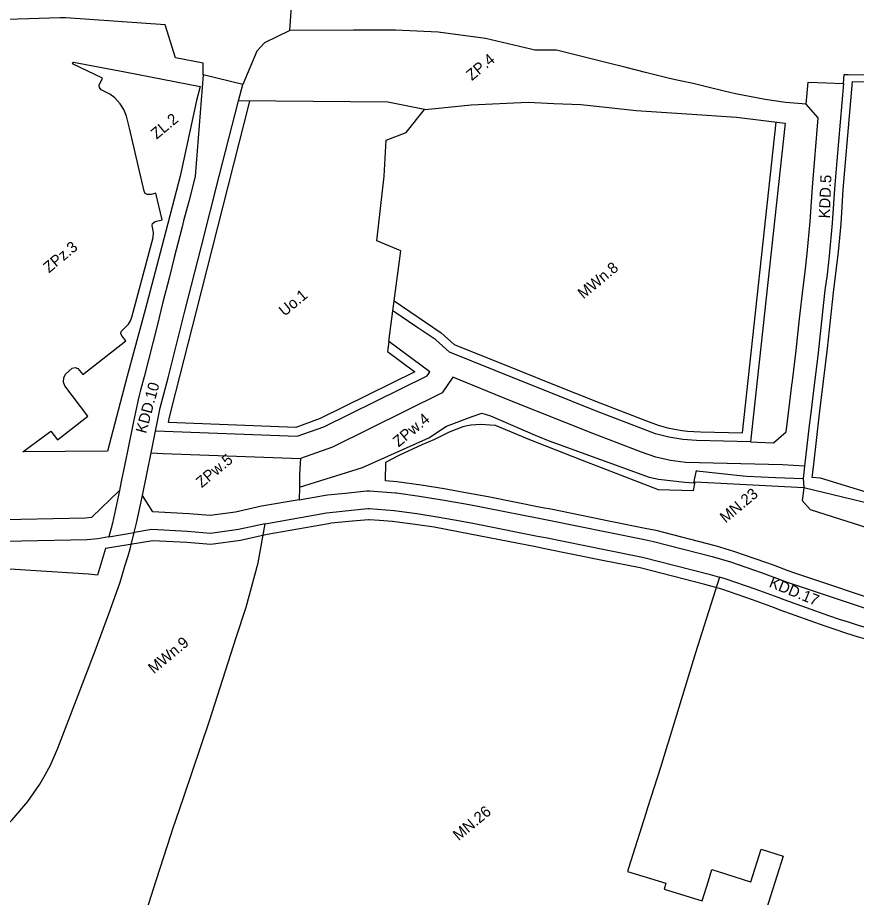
# Model space of a CAD drawing. Extents: x 7418616 to 7420822, y 5550745 to 5553106.
# Drawn here: x 7419553.4 to 7419932.5, y 5552057.3 to 5552455 of the extents above; entities that cross this region are included whole.
import ezdxf

# ---------------------------------------------------------------- set-up
doc = ezdxf.new("R2010")
doc.units = 0
for name, color, linetype in [('linie rozgraniczające', 7, 'Continuous'), ('nieprzekraczalne linie zabudowy', 7, 'Continuous'), ('przeznaczenia terenów', 7, 'Continuous')]:
    doc.layers.add(name, color=color, linetype=linetype)

msp = doc.modelspace()

# ---------------------------------------------------------------- linework, layer by layer
at = {"layer": 'linie rozgraniczające'}
for p, q in [((7419655.14, 5552424.74), (7419637.2, 5552429.07)), ((7419653.25, 5552417.32), (7419655.14, 5552424.74)), ((7419609.8, 5552239.02), (7419613.73, 5552258.19)), ((7419909.13, 5552252.2), (7419908.48, 5552246.57)), ((7419680.75, 5552242.72), (7419680.72, 5552237.05)), ((7419594.63, 5552220.26), (7419606.15, 5552222.19))]:
    msp.add_line(p, q, dxfattribs=at)
for points in [[(7419676.51, 5552449.1), (7419678.57, 5552479.45), (7419677.27, 5552480.3), (7419678.28, 5552486.89), (7419680.25, 5552499.71)], [(7419637.2, 5552429.07), (7419637.23, 5552434.4), (7419624.8, 5552436.75), (7419620.16, 5552451.72), (7419575.16, 5552454.94), (7419572.63, 5552454.93), (7419539.06, 5552453.86), (7419527.6, 5552453.48), (7419520.77, 5552453.24)], [(7419676.51, 5552449.1), (7419664.95, 5552443.58), (7419661.56, 5552439.85), (7419655.14, 5552424.74)], [(7419909.82, 5552415.87), (7419900.43, 5552416.68), (7419891.31, 5552417.98), (7419877.93, 5552420.55), (7419872.75, 5552421.81), (7419865.43, 5552423.52), (7419858.74, 5552425.16), (7419852.81, 5552426.42), (7419848.03, 5552427.53), (7419837.21, 5552430.25), (7419828.49, 5552432.39), (7419819.88, 5552434.54), (7419797.04, 5552440.3), (7419787.21, 5552440.32), (7419785.3, 5552440.79), (7419764.88, 5552445.51), (7419743.46, 5552448.48), (7419724.18, 5552449.27), (7419705.17, 5552449.29), (7419676.51, 5552449.1)], [(7419635.87, 5552423.79), (7419634.27, 5552417.47), (7419626.89, 5552383.27), (7419618.55, 5552351.58), (7419611.08, 5552322.83), (7419602.9, 5552292.94), (7419594.08, 5552258.93), (7419555.81, 5552258.67), (7419568.35, 5552268.03), (7419571.41, 5552264.07), (7419585.22, 5552274.87), (7419574.68, 5552288.52), (7419574.2, 5552290.15), (7419574.25, 5552292.07), (7419574.98, 5552293.76), (7419578.12, 5552296.52), (7419579.38, 5552296.83), (7419580.56, 5552296.42), (7419582.84, 5552293.71), (7419602.38, 5552308.85), (7419600.59, 5552310.93), (7419600.09, 5552312.11), (7419600.17, 5552313.11), (7419601.2, 5552314.22), (7419603.46, 5552316.36), (7419604.45, 5552317.98), (7419605.1, 5552319.53), (7419614.72, 5552355.64), (7419614.79, 5552357.91), (7419614.16, 5552361.07), (7419614.43, 5552361.98), (7419615.53, 5552362.83), (7419618.69, 5552363.56), (7419615.85, 5552375.59), (7419613.7, 5552375.08), (7419612.02, 5552374.97), (7419611.05, 5552375.52), (7419610.54, 5552376.48), (7419603.94, 5552404.96), (7419602.6, 5552410.38), (7419601.35, 5552413.5), (7419599.78, 5552416.05), (7419597.39, 5552418.67), (7419595.14, 5552420.35), (7419591.15, 5552422.37), (7419590.41, 5552423.44), (7419590.34, 5552424.44), (7419591.77, 5552427.62), (7419578.26, 5552434.14), (7419578.62, 5552434.87), (7419601.94, 5552430.49), (7419635.87, 5552423.79)], [(7419637.2, 5552429.07), (7419633.61, 5552383.28), (7419632.7, 5552379.55), (7419630.74, 5552371.82), (7419629.63, 5552367.54), (7419628.44, 5552363.09), (7419627.81, 5552360.42), (7419626.78, 5552356.27), (7419624.24, 5552346.61), (7419621.91, 5552337.24), (7419619.1, 5552326.42), (7419618.18, 5552322.59), (7419616.56, 5552316.21), (7419610.56, 5552292.64), (7419609, 5552286.57), (7419608.25, 5552283.56), (7419607.54, 5552280.89), (7419605.79, 5552272.42), (7419605.21, 5552269.46), (7419601.88, 5552253.18), (7419600.26, 5552245.3), (7419599.4, 5552241.21)], [(7419926.65, 5552425.28), (7419926.99, 5552429.22), (7419928.76, 5552429.22), (7419986.92, 5552428.2), (7419992.14, 5552428.07)], [(7419926.65, 5552425.28), (7419923.67, 5552390.24), (7419922.59, 5552377.55), (7419921.62, 5552362.03), (7419920.27, 5552347.29), (7419919.24, 5552338.88), (7419918.32, 5552331.81), (7419916.67, 5552317.69), (7419915.2, 5552303.38), (7419913.27, 5552287.55), (7419911.9, 5552276.31), (7419911.24, 5552270.55), (7419909.13, 5552252.2)], [(7419909.82, 5552415.87), (7419910.67, 5552425.86), (7419918.93, 5552425.58), (7419926.65, 5552425.28)], [(7419613.73, 5552258.19), (7419617.91, 5552278.6), (7419621.38, 5552292.22), (7419629.02, 5552322.23), (7419636.54, 5552351.71), (7419644.58, 5552383.29), (7419653.25, 5552417.32)], [(7419737.36, 5552413.39), (7419720.72, 5552416.8), (7419653.25, 5552417.32)], [(7419737.36, 5552413.39), (7419742.2, 5552413.9), (7419758.46, 5552415.6), (7419784.22, 5552416.78), (7419795.83, 5552416.18), (7419808, 5552415.75), (7419820.55, 5552414.36), (7419832.99, 5552413), (7419855.82, 5552411.45), (7419878.31, 5552409.93), (7419900.26, 5552407.22), (7419884.62, 5552263.16)], [(7419884.62, 5552263.16), (7419887.61, 5552263.09), (7419895.02, 5552262.82), (7419900.84, 5552267.68), (7419901.97, 5552277.48), (7419903.36, 5552288.9), (7419903.64, 5552290.74), (7419905.26, 5552304.48), (7419906.73, 5552318.78), (7419908.4, 5552333.04), (7419909.32, 5552340.13), (7419910.33, 5552348.35), (7419911.65, 5552362.8), (7419912.62, 5552378.29), (7419915.29, 5552409.72), (7419909.82, 5552415.87)], [(7419723.03, 5552322.49), (7419726.58, 5552349.5), (7419715.72, 5552354.09), (7419719.02, 5552383.35), (7419720, 5552399.58), (7419728.99, 5552403.07), (7419737.36, 5552413.39)], [(7419615.76, 5552268.12), (7419679.71, 5552265.74), (7419691.77, 5552270.01), (7419738.49, 5552293.11), (7419739.7, 5552294.88), (7419721.21, 5552308.61), (7419723.03, 5552322.49)], [(7419884.62, 5552263.16), (7419860.31, 5552263.77), (7419854.02, 5552264.21), (7419847.79, 5552265.26), (7419841.7, 5552266.89), (7419835.79, 5552269.1), (7419814.55, 5552277.26), (7419793.63, 5552285.66), (7419779.64, 5552291.24), (7419748.55, 5552303.81), (7419742.37, 5552309.36), (7419733.9, 5552315.1), (7419723.03, 5552322.49)], [(7419909.13, 5552252.2), (7419899.18, 5552252.82), (7419855.34, 5552253.88), (7419848.54, 5552254.72), (7419841.86, 5552256.26), (7419835.37, 5552258.47), (7419813.36, 5552266.94), (7419775.89, 5552281.97), (7419750.13, 5552292.39), (7419745.26, 5552285.3), (7419695.67, 5552260.78), (7419681.24, 5552255.67)], [(7419680.75, 5552242.72), (7419709.25, 5552251.56), (7419739.21, 5552265), (7419747.26, 5552270.33), (7419758.9, 5552274.73), (7419763.24, 5552276.14), (7419767.19, 5552275.03), (7419787.38, 5552266.3), (7419794.78, 5552263.24), (7419794.9, 5552263.23), (7419838.82, 5552247.27), (7419843.14, 5552246.27), (7419854.97, 5552245.03), (7419859.1, 5552244.71), (7419860.2, 5552250.18), (7419860.41, 5552250.16), (7419881.29, 5552247.85), (7419882.93, 5552247.63), (7419895.93, 5552247.09), (7419908.48, 5552246.57)], [(7419613.73, 5552258.19), (7419619.19, 5552257.99), (7419681.24, 5552255.67)], [(7419681.24, 5552255.67), (7419680.78, 5552248.55), (7419680.75, 5552242.72)], [(7419908.48, 5552246.57), (7419908.77, 5552242.61), (7419957.47, 5552230.82), (7419990.73, 5552222.78)], [(7419512.1, 5552229.24), (7419515.84, 5552228.71), (7419518.93, 5552228.31), (7419536.47, 5552227.92), (7419554.92, 5552228.27), (7419584.16, 5552228.89), (7419586.94, 5552229.19), (7419599.4, 5552241.21)], [(7419599.4, 5552241.21), (7419596.3, 5552226.45), (7419594.63, 5552220.26)], [(7419680.72, 5552237.05), (7419691.7, 5552238.98), (7419693.44, 5552239.27), (7419701.57, 5552240.03), (7419711.17, 5552240.99), (7419712.49, 5552241.03), (7419724.17, 5552240.17), (7419724.68, 5552240.11), (7419735.07, 5552238.72), (7419745.36, 5552237.01), (7419755.83, 5552235.13), (7419760.63, 5552234.23), (7419765.13, 5552233.41), (7419789.73, 5552228.5), (7419793.44, 5552227.81), (7419820.33, 5552222.34), (7419836.79, 5552219.04), (7419840.84, 5552218.19), (7419867.3, 5552211.36), (7419875.6, 5552208.92), (7419889.87, 5552203.98), (7419900, 5552200.28), (7419902.57, 5552199.3), (7419946.92, 5552184.49)], [(7419606.15, 5552222.19), (7419607.21, 5552226.41), (7419609.8, 5552239.02)], [(7419680.72, 5552237.05), (7419663.69, 5552234.06), (7419651.84, 5552231.39), (7419640.44, 5552229.87), (7419630.78, 5552230.63), (7419614.56, 5552231.52), (7419609.8, 5552239.02)], [(7419665.26, 5552226.21), (7419693.08, 5552231.1), (7419694.47, 5552231.33), (7419704.3, 5552232.26), (7419711.7, 5552233), (7419712.37, 5552233.02), (7419723.58, 5552232.19), (7419733.89, 5552230.81), (7419744, 5552229.13), (7419753.46, 5552227.43), (7419759.17, 5552226.37), (7419763.62, 5552225.55), (7419788.41, 5552220.6), (7419791.97, 5552219.95), (7419818.73, 5552214.5), (7419835.86, 5552211.07), (7419865.3, 5552203.61), (7419870.62, 5552202.05)], [(7419594.63, 5552220.26), (7419589.63, 5552219.42), (7419584.8, 5552218.9), (7419555.13, 5552218.27), (7419536.45, 5552217.92), (7419517.97, 5552218.33), (7419509.26, 5552219.54), (7419500.68, 5552221.5), (7419492.31, 5552224.19), (7419484.19, 5552227.59), (7419476.4, 5552231.68)], [(7419590.08, 5551982.51), (7419596.14, 5552002.03), (7419596.33, 5552002.64), (7419609.38, 5552044.09), (7419616.1, 5552064.94), (7419622.82, 5552085.79), (7419623.46, 5552087.79), (7419628.52, 5552102.73), (7419640.17, 5552137.15), (7419652.24, 5552174.78), (7419656.71, 5552188.48), (7419662.12, 5552208.47), (7419665.26, 5552226.21)], [(7419665.26, 5552226.21), (7419653.25, 5552223.51), (7419640.66, 5552221.83), (7419630.25, 5552222.65), (7419614.12, 5552223.53), (7419606.15, 5552222.19)], [(7419489.5, 5552027.77), (7419532.5, 5552072.94), (7419550.98, 5552092.35), (7419557.99, 5552100.66), (7419563.48, 5552108.39), (7419565.89, 5552112.66), (7419568.3, 5552117.09), (7419571.58, 5552124.75), (7419588.49, 5552168.69), (7419594.7, 5552185.4), (7419598.11, 5552195.09), (7419599.69, 5552199.82), (7419601.92, 5552206.93), (7419603.31, 5552211.68), (7419604.21, 5552214.8), (7419606.15, 5552222.19)], [(7419870.62, 5552202.05), (7419859.86, 5552167.77), (7419847.43, 5552127.24), (7419847.03, 5552125.93), (7419843.98, 5552115.92), (7419838.15, 5552097.68), (7419837.36, 5552095.22), (7419829.53, 5552070.5), (7419829.03, 5552068.94), (7419846.45, 5552063.69), (7419845.58, 5552060.93), (7419862.79, 5552055.65), (7419865.66, 5552064.73), (7419867.22, 5552069.82), (7419869.99, 5552068.95), (7419884.71, 5552064.31), (7419884.73, 5552064.37), (7419889.42, 5552079), (7419899.38, 5552075.86), (7419885.13, 5552030.65)], [(7419981.9, 5552150.37), (7419981.07, 5552151.67), (7419979.95, 5552154.09), (7419977.37, 5552159.56), (7419974.89, 5552162.94), (7419971.41, 5552166.55), (7419968.29, 5552169.27), (7419965.64, 5552170.76), (7419943.32, 5552177.2), (7419938.59, 5552178.62), (7419933.5, 5552180.18), (7419928.42, 5552181.83), (7419924.92, 5552182.92), (7419920.1, 5552184.61), (7419899.81, 5552191.79), (7419897.2, 5552192.79), (7419887.17, 5552196.45), (7419873.16, 5552201.3), (7419870.62, 5552202.05)]]:
    msp.add_lwpolyline(points, dxfattribs=at)
at = {"layer": 'nieprzekraczalne linie zabudowy'}
for points in [[(7419948.21, 5552236.99), (7419916.24, 5552246.72), (7419912.54, 5552247.14), (7419913.1, 5552251.73), (7419915.87, 5552275.84), (7419919.43, 5552305.41), (7419922.23, 5552330.78), (7419924.45, 5552349.09), (7419925.61, 5552361.72), (7419926.58, 5552377.26), (7419930.74, 5552426.18), (7419986.85, 5552425.21)], [(7419721.21, 5552308.61), (7419720.61, 5552304.08), (7419733.01, 5552294.86), (7419690.21, 5552273.7), (7419679.09, 5552269.76), (7419621.64, 5552271.9), (7419621.98, 5552273.54), (7419623.08, 5552278.64), (7419634.2, 5552322.32), (7419658.42, 5552417.28)], [(7419723.61, 5552326.93), (7419744.84, 5552312.52), (7419750.7, 5552307.26), (7419781.13, 5552294.95), (7419794.52, 5552289.61), (7419816.52, 5552280.78), (7419837.64, 5552272.68), (7419842.92, 5552270.71), (7419847.09, 5552269.59), (7419850.35, 5552268.89), (7419853.72, 5552268.32), (7419856.23, 5552268.07), (7419859.11, 5552267.86), (7419862.12, 5552267.72), (7419881.04, 5552267.25), (7419896.29, 5552407.71)], [(7419948.41, 5552189.26), (7419904.25, 5552204.01), (7419901.75, 5552204.97), (7419895.06, 5552207.4), (7419891.56, 5552208.69), (7419877.13, 5552213.68), (7419869.32, 5552215.99), (7419868.66, 5552216.17), (7419841.98, 5552223.06), (7419837.83, 5552223.93), (7419821.32, 5552227.24), (7419794.44, 5552232.71), (7419790.67, 5552233.41), (7419766.07, 5552238.32), (7419756.75, 5552240.04), (7419746.21, 5552241.94), (7419735.81, 5552243.67), (7419724.75, 5552245.14), (7419719.68, 5552245.51), (7419719.81, 5552254.08), (7419725.85, 5552257.14), (7419736.26, 5552261.94), (7419741.92, 5552264.46), (7419748.64, 5552267.67), (7419752.07, 5552269.14), (7419754.72, 5552270.1), (7419756.63, 5552270.62), (7419758.47, 5552270.97), (7419762.59, 5552271.16), (7419769.24, 5552270.73), (7419784.8, 5552264.32), (7419808.6, 5552254.91), (7419842.87, 5552241.64), (7419858.95, 5552241.14), (7419859.6, 5552245.13), (7419908.77, 5552242.61)], [(7419908.77, 5552242.61), (7419908.24, 5552238.77), (7419907.94, 5552236.75), (7419911.69, 5552232.6), (7419944.34, 5552222.27)], [(7419937.16, 5552173.83), (7419932.03, 5552175.4), (7419926.84, 5552177.09), (7419923.35, 5552178.17), (7419918.44, 5552179.89), (7419898.08, 5552187.1), (7419895.45, 5552188.11), (7419885.48, 5552191.74), (7419871.63, 5552196.54), (7419863.97, 5552198.79), (7419834.75, 5552206.19), (7419817.75, 5552209.6), (7419790.97, 5552215.05), (7419787.57, 5552215.67), (7419762.68, 5552220.64), (7419752.56, 5552222.51), (7419741.64, 5552224.67), (7419733.15, 5552225.86), (7419723.93, 5552227.09), (7419722.89, 5552227.24), (7419722.66, 5552227.24), (7419716.97, 5552227.67), (7419712.24, 5552228.01), (7419712.02, 5552228.01), (7419704.78, 5552227.28), (7419695.11, 5552226.37), (7419693.9, 5552226.17), (7419666.24, 5552221.31), (7419654.13, 5552218.58), (7419640.8, 5552216.8), (7419629.92, 5552217.66), (7419614.48, 5552218.51), (7419593.06, 5552214.93), (7419589.52, 5552202.91), (7419585.47, 5552203.41), (7419507.07, 5552208.43)]]:
    msp.add_lwpolyline(points, dxfattribs=at)

# ---------------------------------------------------------------- texts
at = {"layer": 'przeznaczenia terenów'}
for s, rotation, p in [('ZP.4', 39.8439, (7419758.73, 5552426.25)), ('ZL.2', 39.8439, (7419616.24, 5552399.77)), ('KDD.5', 87.7739, (7419920.49, 5552364.16)), ('ZPz.3', 39.8439, (7419567.6, 5552339.33)), ('MWn.8', 39.8439, (7419809.14, 5552327.56)), ('Uo.1', 39.8439, (7419674.07, 5552319.72)), ('KDD.10', 74.7871, (7419611.46, 5552266.71)), ('ZPw.4', 39.8439, (7419725.59, 5552260.59)), ('ZPw.5', 39.8439, (7419636.61, 5552242.19)), ('MN.23', 39.8439, (7419873.4, 5552226.28)), ('KDD.17', 337.8354, (7419892.67, 5552197.79)), ('MWn.9', 39.8439, (7419614.98, 5552158.11)), ('MN.26', 39.8439, (7419752.75, 5552082.65))]:
    msp.add_text(s, height=5, rotation=rotation, dxfattribs=at).set_placement(p)

doc.saveas('drawing.dxf')
